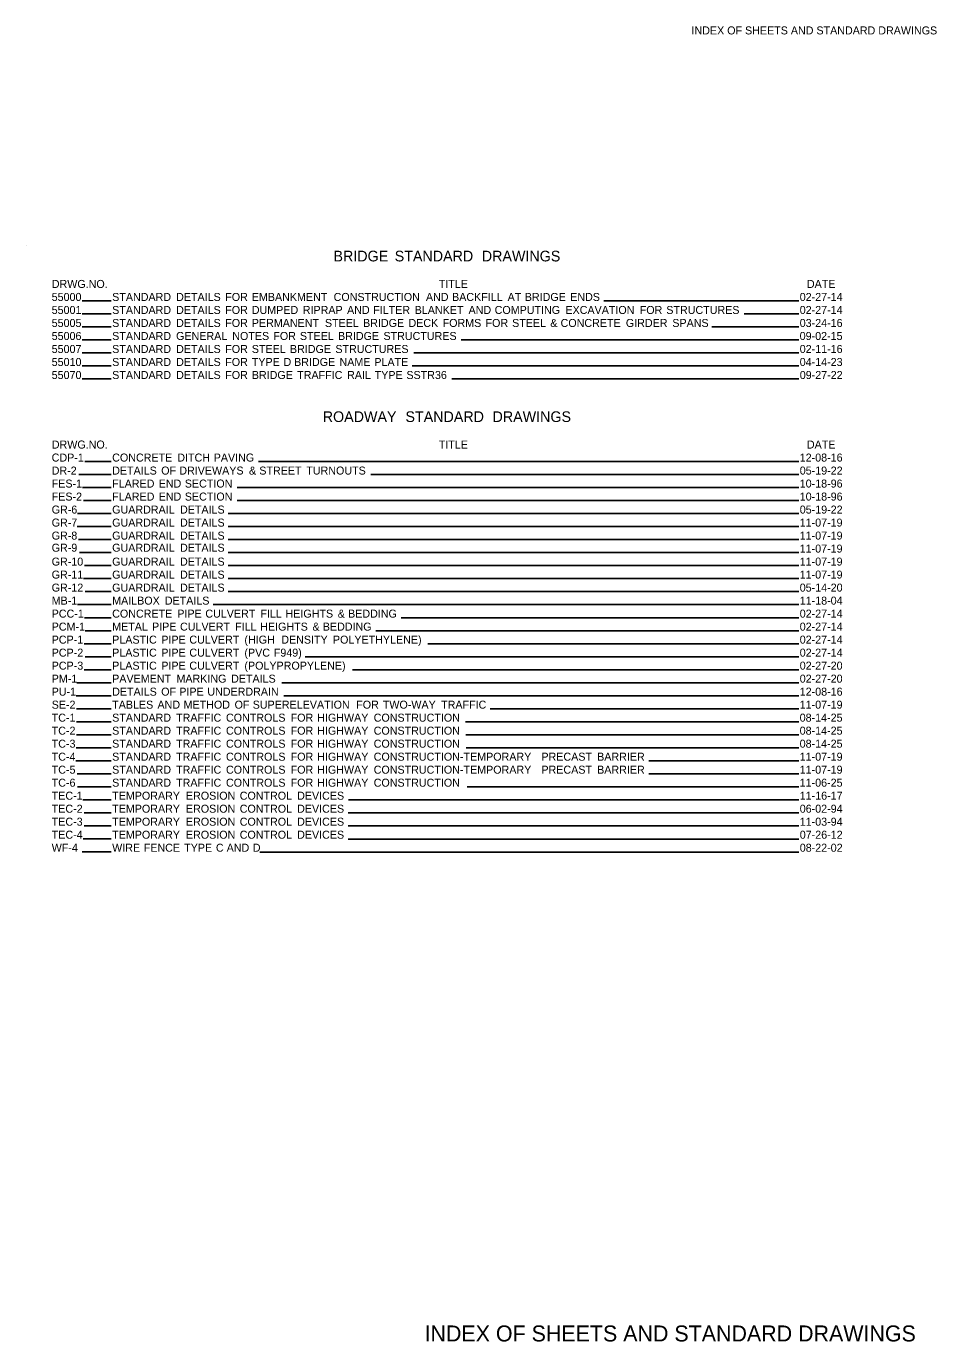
# Model space of a CAD drawing. Extents: x 2661 to 4126, y 471 to 1457.
# Drawn here: x 3444 to 4126, y 471 to 1457 of the extents above; entities that cross this region are included whole.
import ezdxf

# ---------------------------------------------------------------- set-up
doc = ezdxf.new("R2010")
doc.units = 0
for name, color, linetype in [('Default', 7, 'Continuous'), ('R_Draft', 7, 'Continuous'), ('R_Logo', 7, 'Continuous')]:
    doc.layers.add(name, color=color, linetype=linetype)

msp = doc.modelspace()

# ---------------------------------------------------------------- linework, layer by layer
at = {"layer": 'Default'}
for p, q in [((3443.64, 1292.02), (3443.64, 1292.02)), ((3485.53, 1250.86), (3507.17, 1250.86)), ((3876.53, 1250.86), (4022.63, 1250.86)), ((3485.53, 1241.11), (3507.17, 1241.11)), ((3981.74, 1241.11), (4022.63, 1241.11)), ((3485.53, 1231.36), (3507.17, 1231.36)), ((3957.53, 1231.36), (4022.63, 1231.36)), ((3485.53, 1221.61), (3507.17, 1221.61)), ((3769.63, 1221.61), (4022.63, 1221.61)), ((3485.53, 1211.86), (3507.17, 1211.86)), ((3734.14, 1211.86), (4022.63, 1211.86)), ((3485.53, 1202.11), (3507.17, 1202.11)), ((3732.86, 1202.11), (4022.63, 1202.11)), ((3485.53, 1192.36), (3507.17, 1192.36)), ((3762.48, 1192.36), (4022.63, 1192.36)), ((3487.54, 1130.37), (3507.17, 1130.37)), ((3617.62, 1130.37), (4022.63, 1130.37)), ((3483.08, 1120.62), (3507.17, 1120.62)), ((3701.86, 1120.62), (4022.63, 1120.62)), ((3485.68, 1110.87), (3507.17, 1110.87)), ((3601.67, 1110.87), (4022.63, 1110.87)), ((3486.55, 1101.12), (3507.17, 1101.12)), ((3601.67, 1101.12), (4022.63, 1101.12)), ((3481.95, 1091.37), (3507.17, 1091.37)), ((3595.01, 1091.37), (4022.63, 1091.37)), ((3481.82, 1081.62), (3507.17, 1081.62)), ((3595.01, 1081.62), (4022.63, 1081.62)), ((3482.79, 1071.87), (3507.17, 1071.87)), ((3595.01, 1071.87), (4022.63, 1071.87)), ((3483.4, 1062.12), (3507.17, 1062.12)), ((3595.01, 1062.12), (4022.63, 1062.12)), ((3487.37, 1052.37), (3507.17, 1052.37)), ((3595.01, 1052.37), (4022.63, 1052.37)), ((3486.62, 1042.62), (3507.17, 1042.62)), ((3595.01, 1042.62), (4022.63, 1042.62)), ((3487.8, 1032.87), (3507.17, 1032.87)), ((3595.01, 1032.87), (4022.63, 1032.87)), ((3481.97, 1023.12), (3507.17, 1023.12)), ((3583.77, 1023.12), (4022.63, 1023.12)), ((3487.16, 1013.37), (3507.17, 1013.37)), ((3724.54, 1013.37), (4022.63, 1013.37)), ((3487.64, 1003.62), (3507.17, 1003.62)), ((3705.52, 1003.62), (4022.63, 1003.62)), ((3486.97, 993.87), (3507.17, 993.87)), ((3744.44, 993.87), (4022.63, 993.87)), ((3487.81, 984.12), (3507.17, 984.12)), ((3652.55, 984.12), (4022.63, 984.12)), ((3487.04, 974.37), (3507.17, 974.37)), ((3688.03, 974.37), (4022.63, 974.37)), ((3481.42, 964.62), (3507.17, 964.62)), ((3635.04, 964.62), (4022.63, 964.62)), ((3480.93, 954.87), (3507.17, 954.87)), ((3636.7, 954.87), (4022.63, 954.87)), ((3481.18, 945.12), (3507.17, 945.12)), ((3791.24, 945.12), (4022.63, 945.12)), ((3481.14, 935.37), (3507.17, 935.37)), ((3772.84, 935.37), (4022.63, 935.37)), ((3481.27, 925.62), (3507.17, 925.62)), ((3773.06, 925.62), (4022.63, 925.62)), ((3481.11, 915.87), (3507.17, 915.87)), ((3773.23, 915.87), (4022.63, 915.87)), ((3480.7, 906.12), (3507.17, 906.12)), ((3910.28, 906.12), (4022.63, 906.12)), ((3481.67, 896.37), (3507.17, 896.37)), ((3910.28, 896.37), (4022.63, 896.37)), ((3481.9, 886.62), (3507.17, 886.62)), ((3773.97, 886.62), (4022.63, 886.62)), ((3486.11, 876.87), (3507.17, 876.87)), ((3685.13, 876.87), (4022.63, 876.87)), ((3487.08, 867.12), (3507.17, 867.12)), ((3684.9, 867.12), (4022.63, 867.12)), ((3487.08, 857.37), (3507.17, 857.37)), ((3684.9, 857.37), (4022.63, 857.37)), ((3486.29, 847.62), (3507.17, 847.62)), ((3684.9, 847.37), (4022.63, 847.37)), ((3485.53, 837.87), (3507.17, 837.87)), ((3618.77, 837.62), (4022.63, 837.62))]:
    msp.add_line(p, q, dxfattribs=at)

# ---------------------------------------------------------------- texts
for s, height, p in [('BRIDGE', 8, (3673.85, 1280.46)), (' STANDARD', 8, (3716.77, 1280.46)), (' DRAWINGS', 8, (3782.05, 1280.46)), ('DRWG.NO.', 6, (3462.75, 1260.56)), ('TITLE', 6, (3752.74, 1260.56)), ('DATE', 6, (4028.65, 1260.56)), ('55000', 6, (3462.66, 1250.81)), ('STANDARD', 6, (3507.99, 1250.81)), (' DETAILS', 6, (3553.67, 1250.81)), (' FOR', 6, (3590.5, 1250.81)), (' EMBANKMENT', 6, (3610.41, 1250.81)), (' CONSTRUCTION', 6, (3671.73, 1250.81)), (' AND', 6, (3740.91, 1250.81)), (' BACKFILL', 6, (3760.49, 1250.81)), (' AT', 6, (3802.13, 1250.81)), (' BRIDGE', 6, (3815, 1250.81)), (' ENDS', 6, (3849.02, 1250.81)), ('02-27-14', 6, (4023.29, 1250.81)), ('55001', 6, (3462.66, 1241.06)), ('STANDARD', 6, (3507.99, 1241.06)), (' DETAILS', 6, (3553.67, 1241.06)), (' FOR', 6, (3590.5, 1241.06)), (' DUMPED', 6, (3610.41, 1241.06)), (' RIPRAP', 6, (3648.62, 1241.06)), (' AND', 6, (3681.8, 1241.06)), (' FILTER', 6, (3701.38, 1241.06)), (' BLANKET', 6, (3732.48, 1241.06)), (' AND', 6, (3772.84, 1241.06)), (' COMPUTING', 6, (3792.43, 1241.06)), (' EXCAVATION', 6, (3845.46, 1241.06)), (' FOR', 6, (3901.15, 1241.06)), (' STRUCTURES', 6, (3921.06, 1241.06)), ('02-27-14', 6, (4023.29, 1241.06)), ('55005', 6, (3462.66, 1231.31)), ('STANDARD', 6, (3507.99, 1231.31)), (' DETAILS', 6, (3553.67, 1231.31)), (' FOR', 6, (3590.5, 1231.31)), (' PERMANENT', 6, (3610.41, 1231.31)), (' STEEL', 6, (3665.21, 1231.31)), (' BRIDGE', 6, (3693.8, 1231.31)), (' DECK', 6, (3727.83, 1231.31)), (' FORMS', 6, (3753.43, 1231.31)), (' FOR', 6, (3785.59, 1231.31)), (' STEEL', 6, (3805.51, 1231.31)), (' &', 6, (3834.1, 1231.31)), (' CONCRETE', 6, (3841.83, 1231.31)), (' GIRDER', 6, (3890.75, 1231.31)), (' SPANS', 6, (3925.57, 1231.31)), ('03-24-16', 6, (4023.28, 1231.31)), ('55006', 6, (3462.66, 1221.56)), ('STANDARD', 6, (3507.99, 1221.56)), (' GENERAL', 6, (3553.67, 1221.56)), (' NOTES', 6, (3595.77, 1221.56)), (' FOR', 6, (3626.54, 1221.56)), (' STEEL', 6, (3646.45, 1221.56)), (' BRIDGE', 6, (3675.04, 1221.56)), (' STRUCTURES', 6, (3709.07, 1221.56)), ('09-02-15', 6, (4023.25, 1221.56)), ('55007', 6, (3462.66, 1211.81)), ('STANDARD', 6, (3507.99, 1211.81)), (' DETAILS', 6, (3553.67, 1211.81)), (' FOR', 6, (3590.5, 1211.81)), (' STEEL', 6, (3610.41, 1211.81)), (' BRIDGE', 6, (3639, 1211.81)), (' STRUCTURES', 6, (3673.03, 1211.81)), ('02-11-16', 6, (4023.28, 1211.81)), ('55010', 6, (3462.66, 1202.06)), ('STANDARD', 6, (3507.99, 1202.06)), (' DETAILS', 6, (3553.67, 1202.06)), (' FOR', 6, (3590.5, 1202.06)), (' TYPE', 6, (3610.41, 1202.06)), (' D', 6, (3634.19, 1202.06)), (' BRIDGE', 6, (3642.12, 1202.06)), (' NAME', 6, (3676.15, 1202.06)), (' PLATE', 6, (3702.25, 1202.06)), ('04-14-23', 6, (4023.28, 1202.06)), ('55070', 6, (3462.66, 1192.31)), ('STANDARD', 6, (3507.99, 1192.31)), (' DETAILS', 6, (3553.67, 1192.31)), (' FOR', 6, (3590.5, 1192.31)), (' BRIDGE', 6, (3610.41, 1192.31)), (' TRAFFIC', 6, (3644.43, 1192.31)), (' RAIL', 6, (3681.82, 1192.31)), (' TYPE', 6, (3702.49, 1192.31)), (' SSTR36', 6, (3726.27, 1192.31)), ('09-27-22', 6, (4023.31, 1192.31)), ('ROADWAY', 8, (3665.8, 1160.05)), (' STANDARD', 8, (3724.82, 1160.05)), (' DRAWINGS', 8, (3790.09, 1160.05)), ('DRWG.NO.', 6, (3462.75, 1140.15)), ('TITLE', 6, (3752.74, 1140.15)), ('DATE', 6, (4028.65, 1140.15)), ('CDP-1', 6, (3462.66, 1130.4)), ('CONCRETE', 6, (3507.99, 1130.4)), (' DITCH', 6, (3554.59, 1130.4)), (' PAVING', 6, (3581.86, 1130.4)), ('12-08-16', 6, (4023.28, 1130.4)), ('DR-2', 6, (3462.66, 1120.65)), ('DETAILS', 6, (3507.99, 1120.65)), (' OF', 6, (3542.5, 1120.65)), (' DRIVEWAYS', 6, (3556.08, 1120.65)), (' &', 6, (3608.29, 1120.65)), (' STREET', 6, (3616.02, 1120.65)), (' TURNOUTS', 6, (3651.25, 1120.65)), ('05-19-22', 6, (4023.31, 1120.65)), ('FES-1', 6, (3462.66, 1110.9)), ('FLARED', 6, (3507.99, 1110.9)), (' END', 6, (3540.62, 1110.9)), (' SECTION', 6, (3560.2, 1110.9)), ('10-18-96', 6, (4023.28, 1110.9)), ('FES-2', 6, (3462.66, 1101.15)), ('FLARED', 6, (3507.99, 1101.15)), (' END', 6, (3540.62, 1101.15)), (' SECTION', 6, (3560.2, 1101.15)), ('10-18-96', 6, (4023.28, 1101.15)), ('GR-6', 6, (3462.66, 1091.4)), ('GUARDRAIL', 6, (3507.99, 1091.4)), (' DETAILS', 6, (3556.61, 1091.4)), ('05-19-22', 6, (4023.31, 1091.4)), ('GR-7', 6, (3462.66, 1081.65)), ('GUARDRAIL', 6, (3507.99, 1081.65)), (' DETAILS', 6, (3556.61, 1081.65)), ('11-07-19', 6, (4023.27, 1081.65)), ('GR-8', 6, (3462.66, 1071.9)), ('GUARDRAIL', 6, (3507.99, 1071.9)), (' DETAILS', 6, (3556.61, 1071.9)), ('11-07-19', 6, (4023.27, 1071.9)), ('GR-9', 6, (3462.66, 1062.82)), ('GUARDRAIL', 6, (3507.99, 1062.82)), (' DETAILS', 6, (3556.61, 1062.82)), ('11-07-19', 6, (4023.27, 1062.15)), ('GR-10', 6, (3462.66, 1052.4)), ('GUARDRAIL', 6, (3507.99, 1052.4)), (' DETAILS', 6, (3556.61, 1052.4)), ('11-07-19', 6, (4023.27, 1052.4)), ('GR-11', 6, (3462.66, 1042.65)), ('GUARDRAIL', 6, (3507.99, 1042.65)), (' DETAILS', 6, (3556.61, 1042.65)), ('11-07-19', 6, (4023.27, 1042.65)), ('GR-12', 6, (3462.66, 1032.9)), ('GUARDRAIL', 6, (3507.99, 1032.9)), (' DETAILS', 6, (3556.61, 1032.9)), ('05-14-20', 6, (4023.29, 1032.9)), ('MB-1', 6, (3462.66, 1023.15)), ('MAILBOX', 6, (3507.99, 1023.15)), (' DETAILS', 6, (3545.21, 1023.15)), ('11-18-04', 6, (4023.29, 1023.15)), ('PCC-1', 6, (3462.66, 1013.4)), ('CONCRETE', 6, (3507.99, 1013.4)), (' PIPE', 6, (3554.59, 1013.4)), (' CULVERT', 6, (3575.58, 1013.4)), (' FILL', 6, (3616.87, 1013.4)), (' HEIGHTS', 6, (3635.67, 1013.4)), (' &', 6, (3674.83, 1013.4)), (' BEDDING', 6, (3682.56, 1013.4)), ('02-27-14', 6, (4023.29, 1013.4)), ('PCM-1', 6, (3462.66, 1003.65)), ('METAL', 6, (3507.99, 1003.65)), (' PIPE', 6, (3535.65, 1003.65)), (' CULVERT', 6, (3556.63, 1003.65)), (' FILL', 6, (3597.92, 1003.65)), (' HEIGHTS', 6, (3616.72, 1003.65)), (' &', 6, (3655.88, 1003.65)), (' BEDDING', 6, (3663.61, 1003.65)), ('02-27-14', 6, (4023.29, 1003.65)), ('PCP-1', 6, (3462.66, 993.9)), ('PLASTIC', 6, (3507.99, 993.9)), (' PIPE', 6, (3542.6, 993.9)), (' CULVERT', 6, (3563.59, 993.9)), (' (HIGH', 6, (3604.88, 993.9)), ('  DENSITY', 6, (3630.28, 993.9)), (' POLYETHYLENE)', 6, (3671.21, 993.9)), ('02-27-14', 6, (4023.29, 993.9)), ('PCP-2', 6, (3462.66, 984.15)), ('PLASTIC', 6, (3507.99, 984.15)), (' PIPE', 6, (3542.6, 984.15)), (' CULVERT', 6, (3563.59, 984.15)), (' (PVC', 6, (3604.88, 984.15)), (' F949)', 6, (3626.9, 984.15)), ('02-27-14', 6, (4023.29, 984.15)), ('PCP-3', 6, (3462.66, 974.4)), ('PLASTIC', 6, (3507.99, 974.4)), (' PIPE', 6, (3542.6, 974.4)), (' CULVERT', 6, (3563.59, 974.4)), (' (POLYPROPYLENE)', 6, (3604.88, 974.4)), ('02-27-20', 6, (4023.29, 974.4)), ('PM-1', 6, (3462.66, 964.65)), ('PAVEMENT', 6, (3507.99, 964.65)), (' MARKING', 6, (3553.95, 964.65)), (' DETAILS', 6, (3594.88, 964.65)), ('02-27-20', 6, (4023.29, 964.65)), ('PU-1', 6, (3462.66, 954.9)), ('DETAILS', 6, (3507.99, 954.9)), (' OF', 6, (3542.5, 954.9)), (' PIPE', 6, (3556.08, 954.9)), (' UNDERDRAIN', 6, (3577.07, 954.9)), ('12-08-16', 6, (4023.28, 954.9)), ('SE-2', 6, (3462.66, 945.15)), ('TABLES', 6, (3507.99, 945.15)), (' AND', 6, (3539.71, 945.15)), (' METHOD', 6, (3559.29, 945.15)), (' OF', 6, (3597.5, 945.15)), (' SUPERELEVATION', 6, (3611.09, 945.15)), (' FOR', 6, (3688.67, 945.15)), (' TWO-WAY', 6, (3708.59, 945.15)), (' TRAFFIC', 6, (3752.29, 945.15)), ('11-07-19', 6, (4023.27, 945.15)), ('TC-1', 6, (3462.66, 935.4)), ('STANDARD', 6, (3507.99, 935.4)), (' TRAFFIC', 6, (3553.67, 935.4)), (' CONTROLS', 6, (3591.06, 935.4)), (' FOR', 6, (3639.53, 935.4)), (' HIGHWAY', 6, (3659.44, 935.4)), (' CONSTRUCTION', 6, (3701.76, 935.4)), ('08-14-25', 6, (4023.25, 935.4)), ('TC-2', 6, (3462.66, 925.65)), ('STANDARD', 6, (3507.99, 925.65)), (' TRAFFIC', 6, (3553.67, 925.65)), (' CONTROLS', 6, (3591.06, 925.65)), (' FOR', 6, (3639.53, 925.65)), (' HIGHWAY', 6, (3659.44, 925.65)), (' CONSTRUCTION', 6, (3701.76, 925.65)), ('08-14-25', 6, (4023.25, 925.65)), ('TC-3', 6, (3462.66, 915.9)), ('STANDARD', 6, (3507.99, 915.9)), (' TRAFFIC', 6, (3553.67, 915.9)), (' CONTROLS', 6, (3591.06, 915.9)), (' FOR', 6, (3639.53, 915.9)), (' HIGHWAY', 6, (3659.44, 915.9)), (' CONSTRUCTION', 6, (3701.76, 915.9)), ('08-14-25', 6, (4023.25, 915.9)), ('TC-4', 6, (3462.66, 906.15)), ('STANDARD', 6, (3507.99, 906.15)), (' TRAFFIC', 6, (3553.67, 906.15)), (' CONTROLS', 6, (3591.06, 906.15)), (' FOR', 6, (3639.53, 906.15)), (' HIGHWAY', 6, (3659.44, 906.15)), (' CONSTRUCTION-TEMPORARY', 6, (3701.76, 906.15)), (' PRECAST', 6, (3827.46, 906.15)), (' BARRIER', 6, (3869.22, 906.15)), ('11-07-19', 6, (4023.27, 906.15)), ('TC-5', 6, (3462.66, 896.4)), ('STANDARD', 6, (3507.99, 896.4)), (' TRAFFIC', 6, (3553.67, 896.4)), (' CONTROLS', 6, (3591.06, 896.4)), (' FOR', 6, (3639.53, 896.4)), (' HIGHWAY', 6, (3659.44, 896.4)), (' CONSTRUCTION-TEMPORARY', 6, (3701.76, 896.4)), (' PRECAST', 6, (3827.46, 896.4)), (' BARRIER', 6, (3869.22, 896.4)), ('11-07-19', 6, (4023.27, 896.4)), ('TC-6', 6, (3462.66, 886.65)), ('STANDARD', 6, (3507.99, 886.65)), (' TRAFFIC', 6, (3553.67, 886.65)), (' CONTROLS', 6, (3591.06, 886.65)), (' FOR', 6, (3639.53, 886.65)), (' HIGHWAY', 6, (3659.44, 886.65)), (' CONSTRUCTION', 6, (3701.76, 886.65)), ('11-06-25', 6, (4023.25, 886.65)), ('TEC-1', 6, (3462.66, 876.9)), ('TEMPORARY', 6, (3507.99, 876.9)), (' EROSION', 6, (3561.04, 876.9)), (' CONTROL', 6, (3601.35, 876.9)), (' DEVICES', 6, (3644.37, 876.9)), ('11-16-17', 6, (4023.28, 876.9)), ('TEC-2', 6, (3462.66, 867.15)), ('TEMPORARY', 6, (3507.99, 867.15)), (' EROSION', 6, (3561.04, 867.15)), (' CONTROL', 6, (3601.35, 867.15)), (' DEVICES', 6, (3644.37, 867.15)), ('06-02-94', 6, (4023.29, 867.15)), ('TEC-3', 6, (3462.66, 857.4)), ('TEMPORARY', 6, (3507.99, 857.4)), (' EROSION', 6, (3561.04, 857.4)), (' CONTROL', 6, (3601.35, 857.4)), (' DEVICES', 6, (3644.37, 857.4)), ('11-03-94', 6, (4023.29, 857.4)), ('TEC-4', 6, (3462.66, 847.65)), ('TEMPORARY', 6, (3507.99, 847.65)), (' EROSION', 6, (3561.04, 847.65)), (' CONTROL', 6, (3601.35, 847.65)), (' DEVICES', 6, (3644.37, 847.65)), ('07-26-12', 6, (4023.31, 847.65)), ('WF-4', 6, (3462.66, 837.9)), ('WIRE', 6, (3507.99, 837.9)), (' FENCE', 6, (3529.43, 837.9)), (' TYPE', 6, (3559.73, 837.9)), (' C', 6, (3583.51, 837.9)), (' AND', 6, (3591.56, 837.9)), (' D', 6, (3611.14, 837.9)), ('08-22-02', 6, (4023.31, 837.9))]:
    msp.add_text(s, height=height, dxfattribs=at).set_placement(p)
at = {"layer": 'R_Draft'}
msp.add_text('INDEX OF SHEETS AND STANDARD DRAWINGS', height=12, dxfattribs=at).set_placement((3742.09, 470.74))
at = {"layer": 'R_Logo'}
msp.add_text('INDEX OF SHEETS AND STANDARD DRAWINGS', height=6, dxfattribs=at).set_placement((3942.18, 1450.62))

doc.saveas('drawing.dxf')
